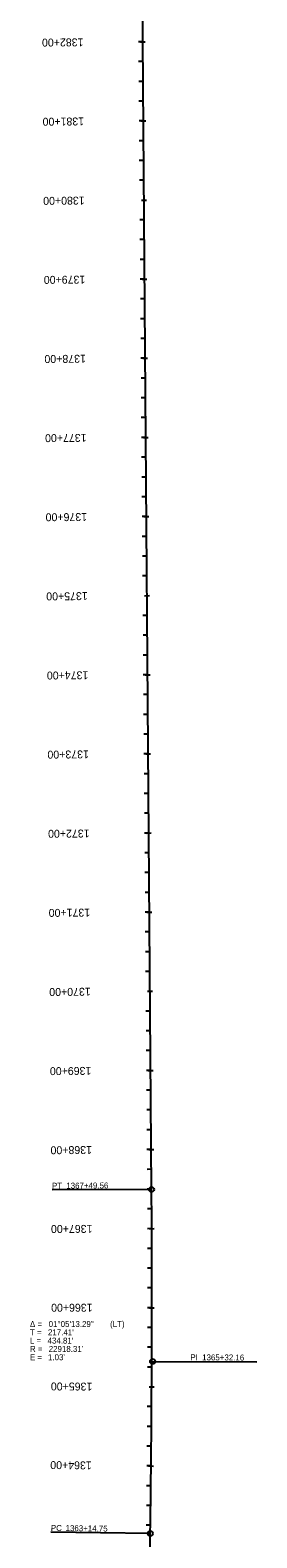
# Model space of a CAD drawing. Extents: x 19548215 to 19548727, y 7547983 to 7562114.
# Drawn here: x 19548233 to 19548520, y 7558308 to 7560213 of the extents above; entities that cross this region are included whole.
import ezdxf

# ---------------------------------------------------------------- set-up
doc = ezdxf.new("R2010")
doc.units = 0
for name, color, linetype in [('Contours Major', 7, 'Continuous'), ('Contours Minor', 7, 'Continuous'), ('Default', 7, 'Continuous'), ('TextAlignment', 7, 'Continuous'), ('TextAlignmentSml', 7, 'Continuous')]:
    doc.layers.add(name, color=color, linetype=linetype)

msp = doc.modelspace()

# ---------------------------------------------------------------- linework, layer by layer
at = {"layer": 'Contours Major'}
for p, q in [((19548375.3, 7560198.6), (19548369.9, 7560198.6)), ((19548376.1, 7560098.6), (19548370.7, 7560098.6)), ((19548373.8, 7559998.6), (19548379.9, 7559998.6)), ((19548377.7, 7559898.6), (19548372.2, 7559898.6)), ((19548378.4, 7559798.6), (19548373, 7559798.6)), ((19548379.2, 7559698.6), (19548373.7, 7559698.6)), ((19548380, 7559598.6), (19548374.5, 7559598.6)), ((19548377.7, 7559498.6), (19548383.8, 7559498.7)), ((19548381.5, 7559398.6), (19548376, 7559398.6)), ((19548382.3, 7559298.6), (19548376.8, 7559298.6)), ((19548383, 7559198.6), (19548377.6, 7559198.6)), ((19548383.8, 7559098.6), (19548378.3, 7559098.6)), ((19548381.5, 7558998.6), (19548387.6, 7558998.7)), ((19548385.3, 7558898.6), (19548379.9, 7558898.6)), ((19548386.1, 7558798.7), (19548380.7, 7558798.6)), ((19548386.7, 7558698.7), (19548381.3, 7558698.6)), ((19548386.9, 7558598.7), (19548381.4, 7558598.7)), ((19548383.6, 7558498.7), (19548389.7, 7558498.6)), ((19548385.9, 7558398.7), (19548380.4, 7558398.7))]:
    msp.add_line(p, q, dxfattribs=at)
at = {"layer": 'Contours Minor'}
for p, q in [((19548386.5, 7558748.2), (19548360.7, 7562103.9)), ((19548377.7, 7557759.4), (19548384.9, 7558313.4))]:
    msp.add_line(p, q, dxfattribs=at)
msp.add_arc((19525468.6, 7558613.4), 22918.3, 359.25012, 0.33714, dxfattribs=at)
at = {"layer": 'Default'}
msp.add_arc((19525468.6, 7558613.4), 22918.3, 359.25012, 0.33714, dxfattribs=at)
at = {"layer": 'TextAlignment'}
for p, q in [((19548386.5, 7558748.2), (19548260.5, 7558747.5)), ((19548260.5, 7558747.5), (19548260.5, 7558747.5)), ((19548387.8, 7558530.8), (19548519.8, 7558530.3)), ((19548519.8, 7558530.3), (19548519.8, 7558530.3)), ((19548384.9, 7558313.4), (19548259, 7558315.1)), ((19548259, 7558315.1), (19548259, 7558315.1))]:
    msp.add_line(p, q, dxfattribs=at)
for centre in [(19548386.5, 7558748.2), (19548387.8, 7558530.8), (19548384.9, 7558313.4)]:
    msp.add_circle(centre, 3.12, dxfattribs=at)
at = {"layer": 'TextAlignmentSml'}
for p, q in [((19548372.3, 7560198.6), (19548378.4, 7560198.6)), ((19548375.5, 7560173.6), (19548370.1, 7560173.6)), ((19548375.7, 7560148.6), (19548370.3, 7560148.6)), ((19548375.9, 7560123.6), (19548370.5, 7560123.6)), ((19548373.1, 7560098.6), (19548379.2, 7560098.6)), ((19548376.3, 7560073.6), (19548370.8, 7560073.6)), ((19548376.5, 7560048.6), (19548371, 7560048.6)), ((19548376.7, 7560023.6), (19548371.2, 7560023.6)), ((19548373.8, 7559998.6), (19548379.9, 7559998.6)), ((19548377.1, 7559973.6), (19548371.6, 7559973.6)), ((19548377.3, 7559948.6), (19548371.8, 7559948.6)), ((19548377.5, 7559923.6), (19548372, 7559923.6)), ((19548374.6, 7559898.6), (19548380.7, 7559898.6)), ((19548377.8, 7559873.6), (19548372.4, 7559873.6)), ((19548378, 7559848.6), (19548372.6, 7559848.6)), ((19548378.2, 7559823.6), (19548372.8, 7559823.6)), ((19548375.4, 7559798.6), (19548381.5, 7559798.6)), ((19548378.6, 7559773.6), (19548373.2, 7559773.6)), ((19548378.8, 7559748.6), (19548373.3, 7559748.6)), ((19548379, 7559723.6), (19548373.5, 7559723.6)), ((19548376.1, 7559698.6), (19548382.3, 7559698.6)), ((19548379.4, 7559673.6), (19548373.9, 7559673.6)), ((19548379.6, 7559648.6), (19548374.1, 7559648.6)), ((19548379.8, 7559623.6), (19548374.3, 7559623.6)), ((19548376.9, 7559598.6), (19548383, 7559598.7)), ((19548380.2, 7559573.6), (19548374.7, 7559573.6)), ((19548380.3, 7559548.6), (19548374.9, 7559548.6)), ((19548380.5, 7559523.6), (19548375.1, 7559523.6)), ((19548377.7, 7559498.6), (19548383.8, 7559498.7)), ((19548380.9, 7559473.6), (19548375.5, 7559473.6)), ((19548381.1, 7559448.6), (19548375.7, 7559448.6)), ((19548381.3, 7559423.6), (19548375.8, 7559423.6)), ((19548378.4, 7559398.6), (19548384.6, 7559398.7)), ((19548381.7, 7559373.6), (19548376.2, 7559373.6)), ((19548381.9, 7559348.6), (19548376.4, 7559348.6)), ((19548382.1, 7559323.6), (19548376.6, 7559323.6)), ((19548379.2, 7559298.6), (19548385.3, 7559298.7)), ((19548382.5, 7559273.6), (19548377, 7559273.6)), ((19548382.7, 7559248.6), (19548377.2, 7559248.6)), ((19548382.8, 7559223.6), (19548377.4, 7559223.6)), ((19548380, 7559198.6), (19548386.1, 7559198.7)), ((19548383.2, 7559173.6), (19548377.8, 7559173.6)), ((19548383.4, 7559148.6), (19548378, 7559148.6)), ((19548383.6, 7559123.6), (19548378.2, 7559123.6)), ((19548380.7, 7559098.6), (19548386.9, 7559098.7)), ((19548384, 7559073.6), (19548378.5, 7559073.6)), ((19548384.2, 7559048.6), (19548378.7, 7559048.6)), ((19548384.4, 7559023.6), (19548378.9, 7559023.6)), ((19548381.5, 7558998.6), (19548387.6, 7558998.7)), ((19548384.8, 7558973.6), (19548379.3, 7558973.6)), ((19548385, 7558948.6), (19548379.5, 7558948.6)), ((19548385.2, 7558923.6), (19548379.7, 7558923.6)), ((19548382.3, 7558898.6), (19548388.4, 7558898.7)), ((19548385.5, 7558873.6), (19548380.1, 7558873.6)), ((19548385.7, 7558848.7), (19548380.3, 7558848.6)), ((19548385.9, 7558823.7), (19548380.5, 7558823.6)), ((19548383.1, 7558798.6), (19548389.2, 7558798.7)), ((19548386.3, 7558773.7), (19548380.9, 7558773.6)), ((19548386.5, 7558748.7), (19548381, 7558748.6)), ((19548386.6, 7558723.7), (19548381.2, 7558723.6)), ((19548383.7, 7558698.6), (19548389.8, 7558698.7)), ((19548386.8, 7558673.7), (19548381.4, 7558673.6)), ((19548386.9, 7558648.7), (19548381.4, 7558648.6)), ((19548386.9, 7558623.7), (19548381.4, 7558623.7)), ((19548383.8, 7558598.7), (19548390, 7558598.7)), ((19548386.9, 7558573.7), (19548381.4, 7558573.7)), ((19548386.8, 7558548.7), (19548381.4, 7558548.7)), ((19548386.7, 7558523.7), (19548381.3, 7558523.7)), ((19548383.6, 7558498.7), (19548389.7, 7558498.6)), ((19548386.5, 7558473.7), (19548381, 7558473.7)), ((19548386.3, 7558448.7), (19548380.9, 7558448.7)), ((19548386.1, 7558423.7), (19548380.7, 7558423.7)), ((19548382.8, 7558398.7), (19548389, 7558398.6)), ((19548385.7, 7558373.7), (19548380.2, 7558373.7)), ((19548385.4, 7558348.7), (19548379.9, 7558348.7)), ((19548385.1, 7558323.7), (19548379.6, 7558323.7))]:
    msp.add_line(p, q, dxfattribs=at)

# ---------------------------------------------------------------- texts
at = {"layer": 'Contours Major'}
for s, rotation, p in [('1380+00', 180.441, (19548301.8, 7560003)), ('1375+00', 180.441, (19548305.7, 7559503.1)), ('1370+00', 180.441, (19548309.5, 7559003.1)), ('1365+00', 179.7133, (19548311.6, 7558504))]:
    msp.add_text(s, height=10.02, rotation=rotation, dxfattribs=at).set_placement(p)
at = {"layer": 'TextAlignment'}
for s, rotation, p in [('PT', 0.3371, (19548260.5, 7558749.1)), ('1367+49.56', 0.3371, (19548278.6, 7558749.2)), ('PI ', 359.7936, (19548435.6, 7558532.3)), ('1365+32.16', 359.7936, (19548450.5, 7558532.2)), ('PC', 359.2501, (19548259, 7558316.7)), ('1363+14.75', 359.2501, (19548277.6, 7558316.5))]:
    msp.add_text(s, height=7.5, rotation=rotation, dxfattribs=at).set_placement(p)
for s, p in [('T = ', (19548232.6, 7558563.9)), ('Δ = ', (19548232.6, 7558574.4)), ("217.41'", (19548255.4, 7558563.9)), ('01°05\'13.29"', (19548256.3, 7558574.4)), (' (LT)', (19548331.2, 7558574.4)), ('L = ', (19548232.6, 7558553.4)), ('R = ', (19548232.6, 7558542.9)), ("434.81'", (19548254.9, 7558553.4)), ("22918.31'", (19548256.3, 7558542.9)), ('E = ', (19548232.6, 7558532.4)), ("1.03'", (19548255.4, 7558532.4))]:
    msp.add_text(s, height=7.5, dxfattribs=at).set_placement(p)
at = {"layer": 'TextAlignmentSml'}
for s, rotation, p in [('1382+00', 180.441, (19548300.3, 7560203)), ('1381+00', 180.441, (19548301.1, 7560103)), ('1380+00', 180.441, (19548301.8, 7560003)), ('1379+00', 180.441, (19548302.6, 7559903.1)), ('1378+00', 180.441, (19548303.4, 7559803.1)), ('1377+00', 180.441, (19548304.2, 7559703.1)), ('1376+00', 180.441, (19548304.9, 7559603.1)), ('1375+00', 180.441, (19548305.7, 7559503.1)), ('1374+00', 180.441, (19548306.5, 7559403.1)), ('1373+00', 180.441, (19548307.2, 7559303.1)), ('1372+00', 180.441, (19548308, 7559203.1)), ('1371+00', 180.441, (19548308.8, 7559103.1)), ('1370+00', 180.441, (19548309.5, 7559003.1)), ('1369+00', 180.441, (19548310.3, 7558903.1)), ('1368+00', 180.441, (19548311.1, 7558803.1)), ('1367+00', 180.2133, (19548311.7, 7558703.4)), ('1366+00', 179.9633, (19548311.9, 7558603.7)), ('1365+00', 179.7133, (19548311.6, 7558504)), ('1364+00', 179.4633, (19548310.9, 7558404.4))]:
    msp.add_text(s, height=10.02, rotation=rotation, dxfattribs=at).set_placement(p)

doc.saveas('drawing.dxf')
